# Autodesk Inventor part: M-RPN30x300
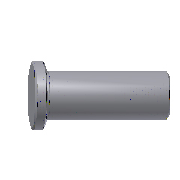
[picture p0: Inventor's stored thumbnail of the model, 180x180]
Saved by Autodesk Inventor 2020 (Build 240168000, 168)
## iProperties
Created: 2019-01
Part Number: M-RPN30x300
Material: SUJ 2
Description: Return Pin
Document SubType Name: Modeling
Designer: LENOVO-CADCIM
Standard Revision: 1
Manufacturer: FUTABA
Language: en-US
Size Designation: 30x300
Categories: <MemberInstance><Categories><Category DisplayName="Mold" InternalName="349578f2-f4d4-4954-8c09-8e99297a61c0" Mnemonic="MOLD"><Category DisplayName="Return Compo
Mass: 6.63789 g
Surface Area: 25.7048 cm^2
Volume: 6.63789 cm^3
Density: 7.85 g/cm^3
Appearance: Aluminum - Dark
IsCustomPart: 1
Author: LENOVO-CADCIM
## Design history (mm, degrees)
body "Solid1"
revolve "Revolution1" stored, may be unused: angle "d41" = 90 deg
revolve "Revolution2" stored, may be unused: angle "d48" = 90 deg
chamfer "Chamfer1" distance "d49" = 0.5; stored, may be unused: second distance "d50" = 2, angle "d51" = 45 deg
sketch "Sketch1"
  geometry: L1 (0, -15)-(0, 62) reference; L2 (0, -4)-(17.5, -4); L3 (17.5, -4)-(17.5, 0); L4 (17.5, 0)-(15, 0); L5 (15, 0)-(15, 296); L6 (15, 296)-(0, 296); L7 (0, 296)-(0, -4); 1 further point
  constraints: 12 end point, 3 perpendicular, 2 parallel, 2 point on line, 1 collinear, 1 horizontal alignment
  dimensions: "d28" = 4 distance between parallel lines of L2 L4 (= H_); "d29" = 35 diameter of L3 L1 (= D); "d31" = 30 diameter of L5 L1 (= d_); "d33" = 300 distance between parallel lines of L2 L6 (= L)
sketch "Sketch2" dims "d31" = 30 (= d_)
  geometry: L1 (15, 296)-(15, 0) reference; L2 (-15, 0)-(15, 0) reference; L3 (15, 0)-(14.8, 0); L4 (14.5, 0.3)-(14.5, 0.9); L5 (14.8, 1.2)-(15, 1.2); L6 (15, 1.2)-(15, 0); L7 (0, -10.275)-(0, 61.212) reference; A1 r 0.3 centre (14.8, 0.9) between (14.8, 1.2) and (14.5, 0.9); A2 r 0.3 centre (14.8, 0.3) between (14.5, 0.3) and (14.8, 0); 1 further point
  constraints: 8 end point, 4 point on circle, 4 tangent, 2 centre point, 2 parallel, 1 equal radius, 1 horizontal, 1 perpendicular
  dimensions: "d45" = 0.3 radius of A1; "d46" = 1.2 distance between parallel lines of L2 L5; "d47" = 0.5 distance between parallel lines of L4 L1
other parameters: "d_" = 30 [user parameter; used in 1 equation term], "L" = 300 [user parameter; used in 1 equation term], "D" = 35 [user parameter; used in 1 equation term], "H_" = 4 [user parameter; used in 1 equation term], "d44" = 0, "d52" = 0, "d53" = 0
